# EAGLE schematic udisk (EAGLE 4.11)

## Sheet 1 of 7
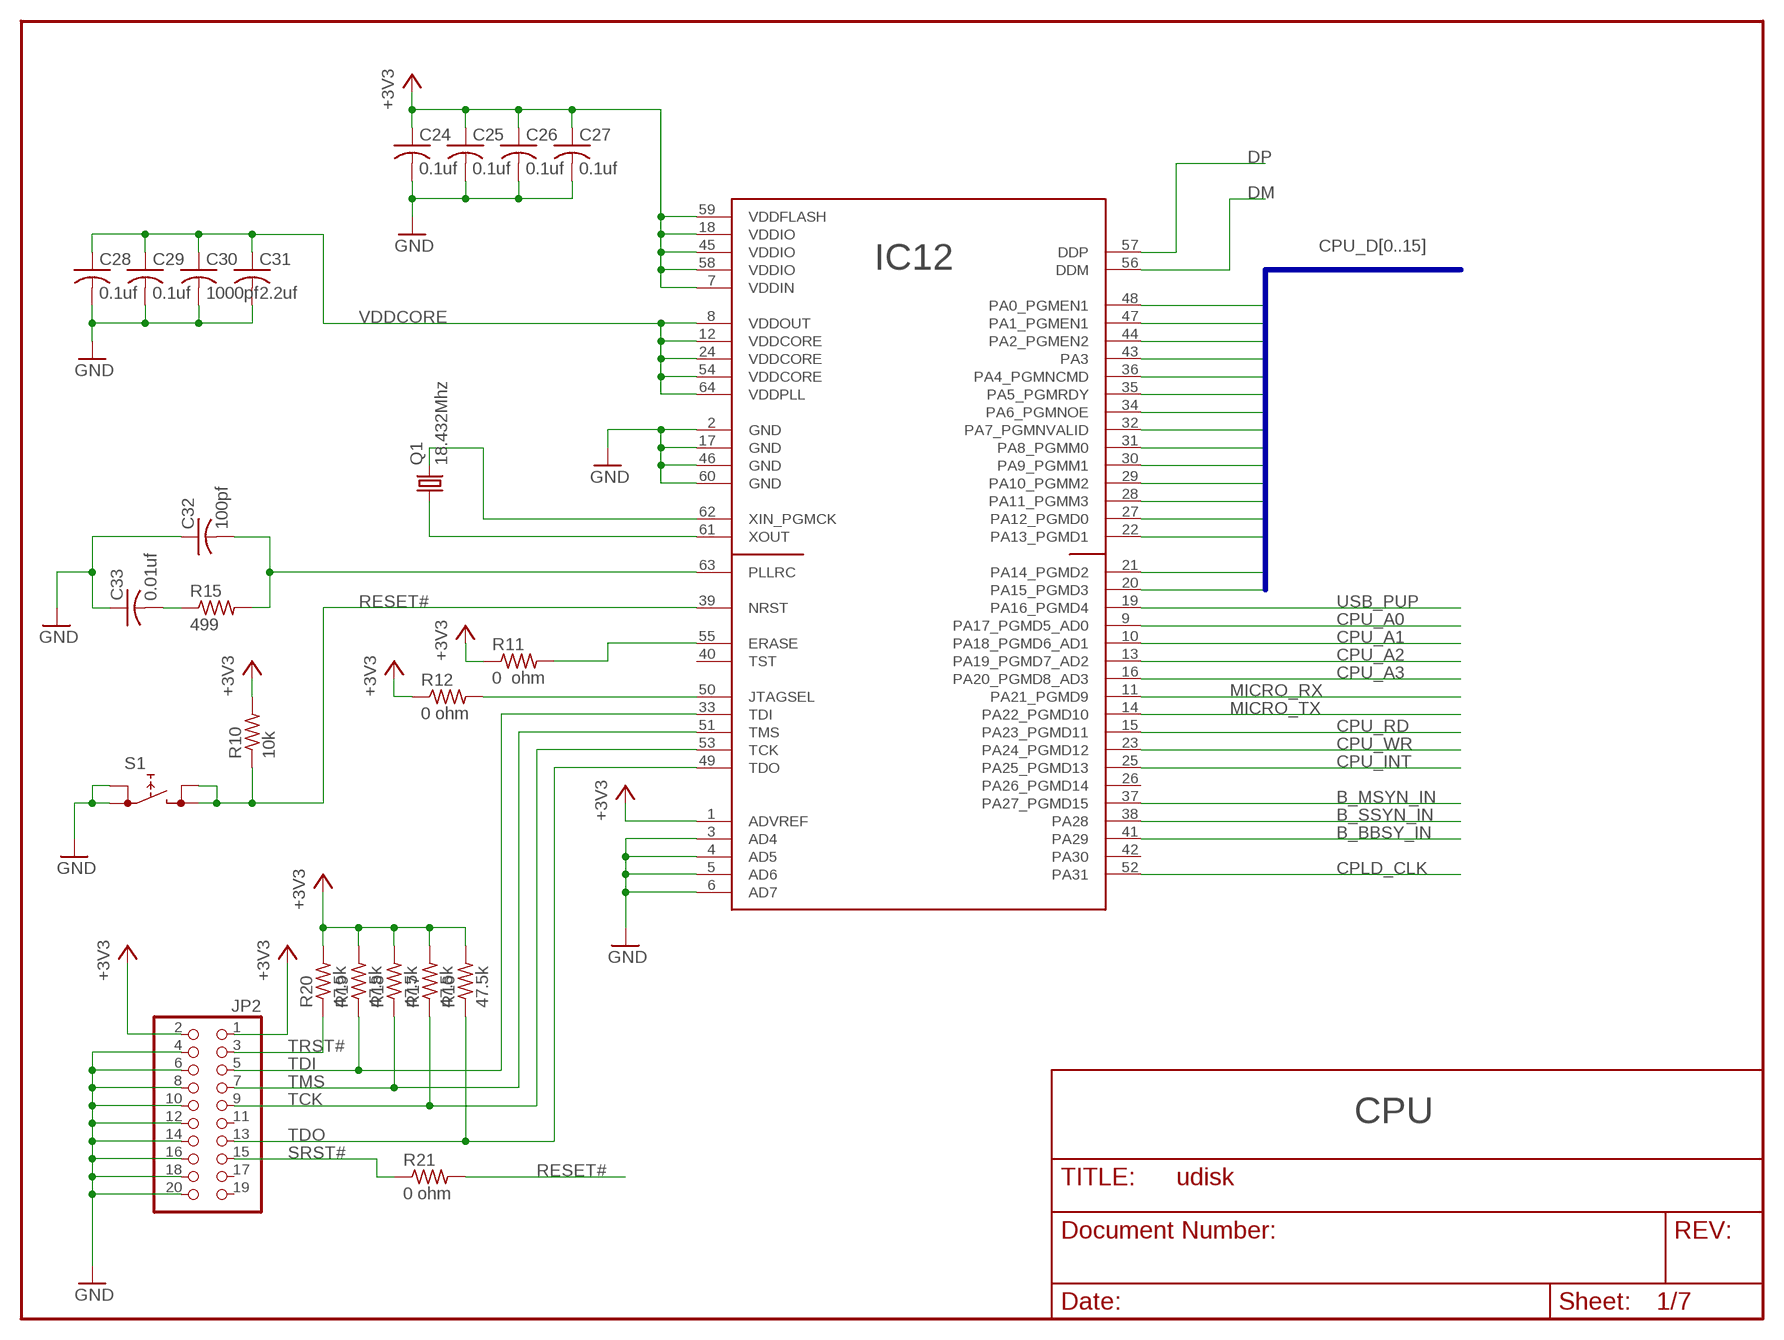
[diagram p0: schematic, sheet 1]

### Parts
C24  0.1uf  C-USC0603  [C0603]
C25  0.1uf  C-USC0603  [C0603]
C26  0.1uf  C-USC0603  [C0603]
C27  0.1uf  C-USC0603  [C0603]
C28  0.1uf  C-USC0603  [C0603]
C29  0.1uf  C-USC0603  [C0603]
C30  1000pf  C-USC0805  [C0805]
C31  2.2uf  C-USC1206  [C1206]
C32  100pf  C-USC0805  [C0805]
C33  0.01uf  C-USC0805  [C0805]
IC12  AT91SAM7S64_LQFP64  [LQFP64]
JP2  PINHD-2X10  [2X10]
Q1  18.432Mhz  CTS406  [SM406]
R10  10k  R-US_R0805  [R0805]
R11  0 ohm  R-US_R0805  [R0805]
R12  0 ohm  R-US_R0805  [R0805]
R15  499  R-US_M0805  [M0805]
R16  47.5k  R-US_R0805  [R0805]
R17  47.5k  R-US_R0805  [R0805]
R18  47.5k  R-US_R0805  [R0805]
R19  47.5k  R-US_R0805  [R0805]
R20  47.5k  R-US_R0805  [R0805]
R21  0 ohm  R-US_R0805  [R0805]
S1  KSC241J  [KSC241J]

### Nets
+3V3: C24.1 C25.1 C26.1 C27.1 IC12.1(ADVREF) IC12.7(VDDIN) IC12.18(VDDIO) IC12.45(VDDIO) IC12.58(VDDIO) IC12.59(VDDFLASH) JP2.1 JP2.2 R10.2 R11.1 R12.1 R16.2 R17.2 R18.2 R19.2 R20.2 ; also sheet 2,5,6,7
B_BBSY_IN: IC12.41(PA29) ; also sheet 2,3
B_MSYN_IN: IC12.37(PA27_PGMD15) ; also sheet 2,3
B_SSYN_IN: IC12.38(PA28) ; also sheet 2,3
CPLD_CLK: IC12.52(PA31) ; also sheet 2
CPU_A0: IC12.9(PA17_PGMD5_AD0) ; also sheet 2,6
CPU_A1: IC12.10(PA18_PGMD6_AD1) ; also sheet 2,6
CPU_A2: IC12.13(PA19_PGMD7_AD2) ; also sheet 2,6
CPU_A3: IC12.16(PA20_PGMD8_AD3) ; also sheet 2
CPU_D0: IC12.48(PA0_PGMEN1) ; also sheet 2,6
CPU_D1: IC12.47(PA1_PGMEN1) ; also sheet 2,6
CPU_D2: IC12.44(PA2_PGMEN2) ; also sheet 2,6
CPU_D3: IC12.43(PA3) ; also sheet 2,6
CPU_D4: IC12.36(PA4_PGMNCMD) ; also sheet 2,6
CPU_D5: IC12.35(PA5_PGMRDY) ; also sheet 2,6
CPU_D6: IC12.34(PA6_PGMNOE) ; also sheet 2,6
CPU_D7: IC12.32(PA7_PGMNVALID) ; also sheet 2,6
CPU_D8: IC12.31(PA8_PGMM0) ; also sheet 2,6
CPU_D9: IC12.30(PA9_PGMM1) ; also sheet 2,6
CPU_D10: IC12.29(PA10_PGMM2) ; also sheet 2,6
CPU_D11: IC12.28(PA11_PGMM3) ; also sheet 2,6
CPU_D12: IC12.27(PA12_PGMD0) ; also sheet 2,6
CPU_D13: IC12.22(PA13_PGMD1) ; also sheet 2,6
CPU_D14: IC12.21(PA14_PGMD2) ; also sheet 2,6
CPU_D15: IC12.20(PA15_PGMD3) ; also sheet 2,6
CPU_INT: IC12.25(PA25_PGMD13) ; also sheet 2
CPU_RD: IC12.15(PA23_PGMD11) ; also sheet 2
CPU_WR: IC12.23(PA24_PGMD12) ; also sheet 2
DM: IC12.56(DDM) ; also sheet 7
DP: IC12.57(DDP) ; also sheet 7
GND: C24.2 C25.2 C26.2 C27.2 C28.2 C29.2 C30.2 C31.2 C32.1 C33.1 IC12.2(GND) IC12.3(AD4) IC12.4(AD5) IC12.5(AD6) IC12.6(AD7) IC12.17(GND) IC12.46(GND) IC12.60(GND) JP2.4 JP2.6 JP2.8 JP2.10 JP2.12 JP2.14 JP2.16 JP2.18 JP2.20 S1.P1 S1.P2 ; also sheet 2,3,4,5,6,7
MICRO_RX: IC12.11(PA21_PGMD9) ; also sheet 5
MICRO_TX: IC12.14(PA22_PGMD10) ; also sheet 5
N$21: IC12.55(ERASE) R11.2
N$22: IC12.50(JTAGSEL) R12.2
N$24: IC12.62(XIN_PGMCK) Q1.3
N$29: IC12.61(XOUT) Q1.1
N$30: C32.2 IC12.63(PLLRC) R15.2
N$32: C33.2 R15.1
RESET#: IC12.39(NRST) R10.1 R21.2 S1.P3 S1.P4
SRST#: JP2.15 R21.1
TCK: IC12.53(TCK) JP2.9 R17.1
TDI: IC12.33(TDI) JP2.5 R19.1
TDO: IC12.49(TDO) JP2.13 R16.1
TMS: IC12.51(TMS) JP2.7 R18.1
TRST#: JP2.3 R20.1
USB_PUP: IC12.19(PA16_PGMD4) ; also sheet 7
VDDCORE: C28.1 C29.1 C30.1 C31.1 IC12.8(VDDOUT) IC12.12(VDDCORE) IC12.24(VDDCORE) IC12.54(VDDCORE) IC12.64(VDDPLL)
Unconnected: IC12.26(PA26_PGMD14) IC12.40(TST) IC12.42(PA30) JP2.11 JP2.17 JP2.19

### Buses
CPU_D[0..15]

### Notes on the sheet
- CPU

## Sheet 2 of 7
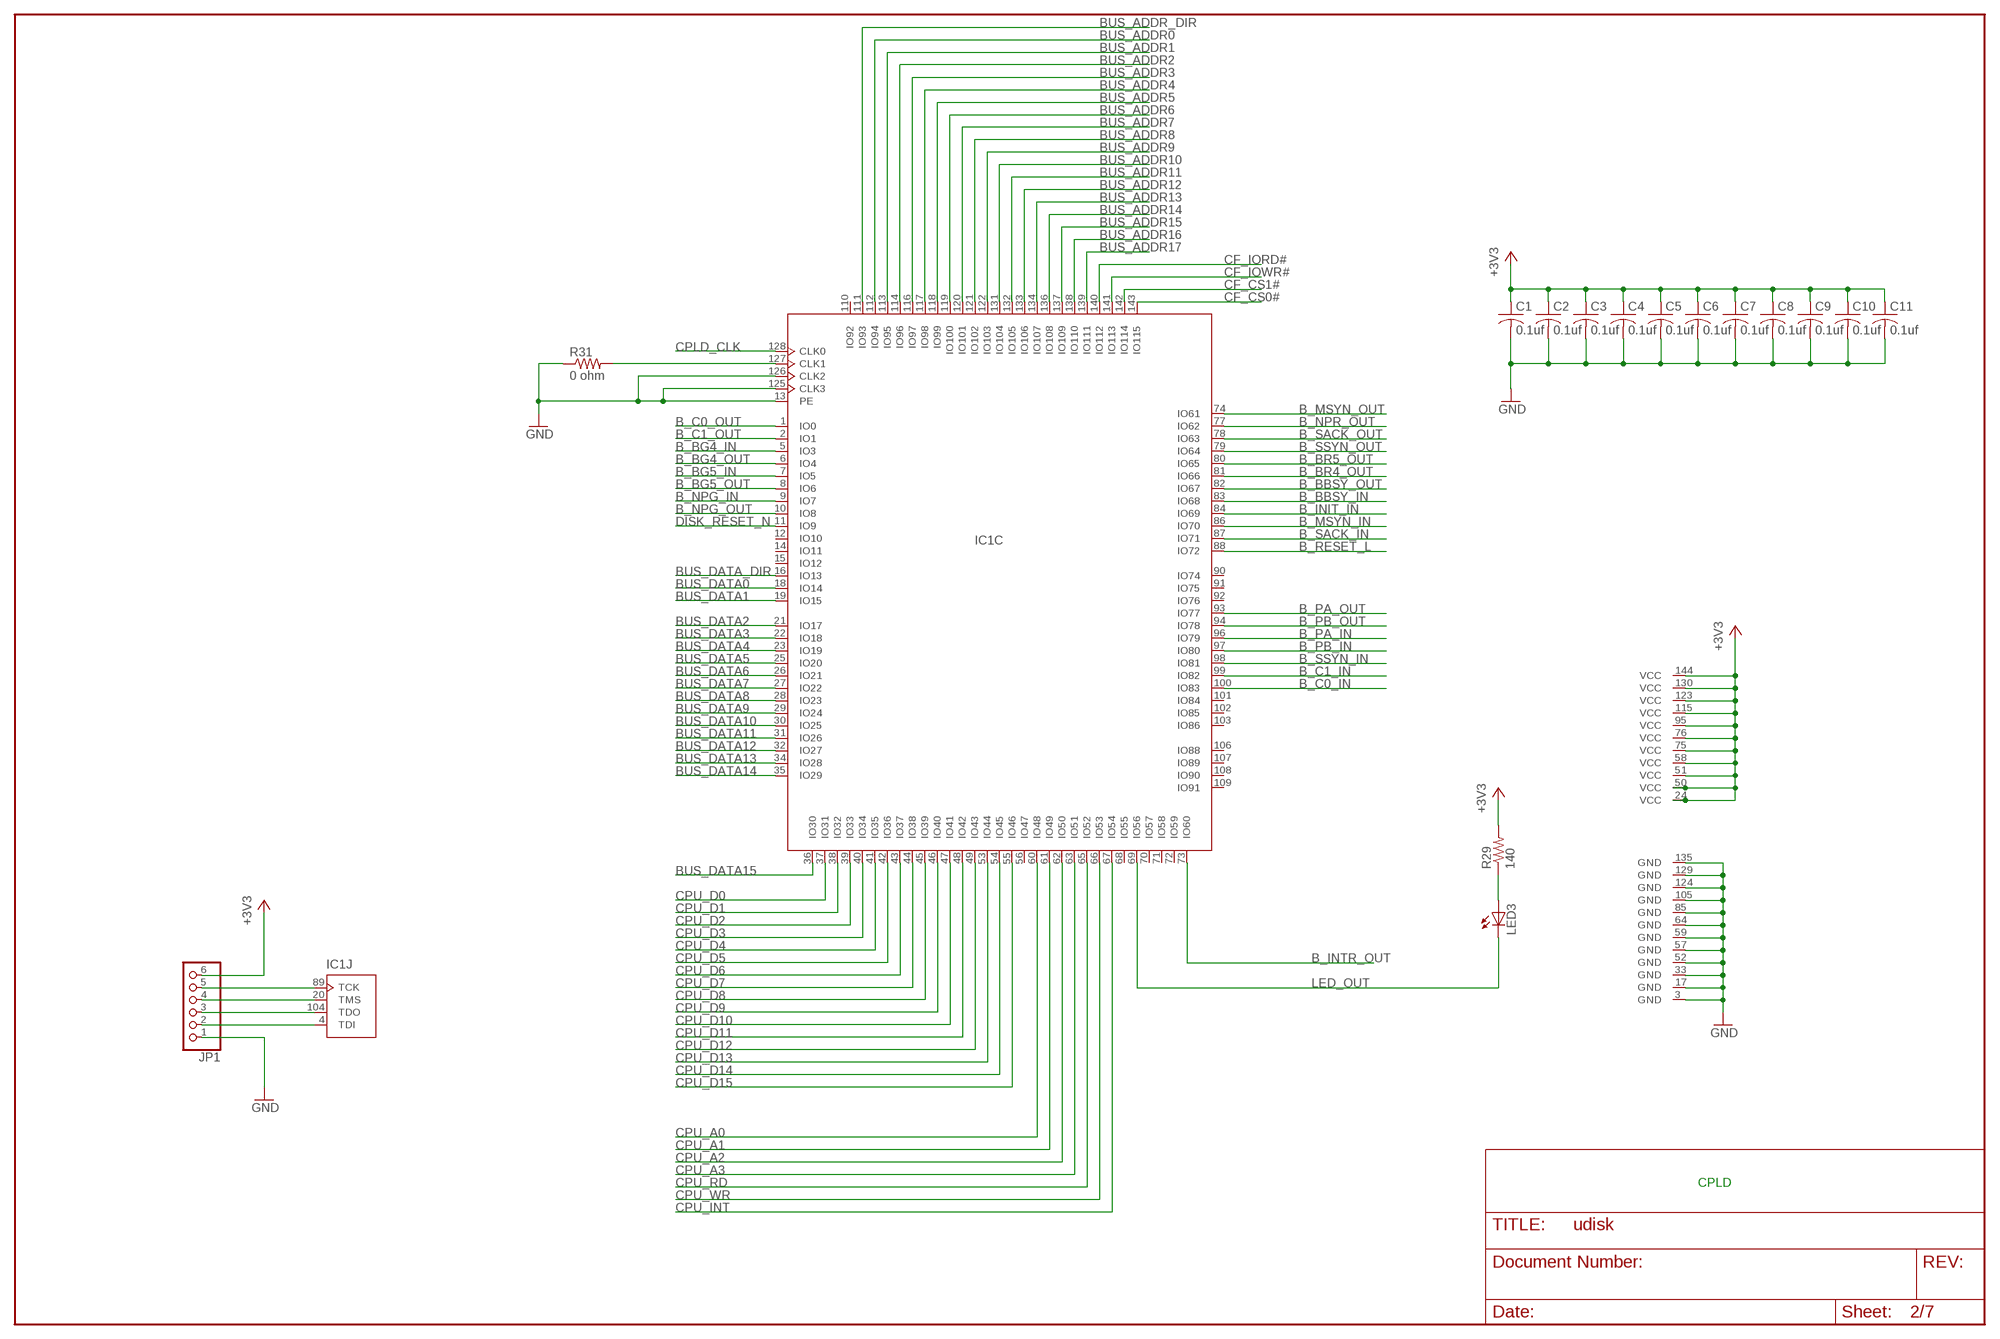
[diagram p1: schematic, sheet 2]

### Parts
C1  0.1uf  C-USC0603  [C0603]
C2  0.1uf  C-USC0603  [C0603]
C3  0.1uf  C-USC0603  [C0603]
C4  0.1uf  C-USC0603  [C0603]
C5  0.1uf  C-USC0603  [C0603]
C6  0.1uf  C-USC0603  [C0603]
C7  0.1uf  C-USC0603  [C0603]
C8  0.1uf  C-USC0603  [C0603]
C9  0.1uf  C-USC0603  [C0603]
C10  0.1uf  C-USC0603  [C0603]
C11  0.1uf  C-USC0603  [C0603]
IC1  XCR3256XLTQ144  [TQ144]
JP1  PINHD-1X6  [1X06]
LED3  LEDB156  [Q62902-B156]
R29  140  R-US_R0805  [R0805]
R31  0 ohm  R-US_R0805  [R0805]

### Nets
+3V3: C1.1 C2.1 C3.1 C4.1 C5.1 C6.1 C7.1 C8.1 C9.1 C10.1 C11.1 IC1.24(V1:VCC) IC1.50(V2:VCC) IC1.51(V3:VCC) IC1.58(V4:VCC) IC1.75(V5:VCC) IC1.76(V6:VCC) IC1.95(V7:VCC) IC1.115(V8:VCC) IC1.123(V9:VCC) IC1.130(V10:VCC) IC1.144(V11:VCC) JP1.6 R29.2 ; also sheet 1,5,6,7
B_BBSY_IN: IC1.83(C:IO68) ; also sheet 1,3
B_BBSY_OUT: IC1.82(C:IO67) ; also sheet 3
B_BG4_IN: IC1.5(C:IO3) ; also sheet 3
B_BG4_OUT: IC1.6(C:IO4) ; also sheet 3
B_BG5_IN: IC1.7(C:IO5) ; also sheet 3
B_BG5_OUT: IC1.8(C:IO6) ; also sheet 3
B_BR4_OUT: IC1.81(C:IO66) ; also sheet 3
B_BR5_OUT: IC1.80(C:IO65) ; also sheet 3
B_C0_IN: IC1.100(C:IO83) ; also sheet 3
B_C0_OUT: IC1.1(C:IO0) ; also sheet 3
B_C1_IN: IC1.99(C:IO82) ; also sheet 3
B_C1_OUT: IC1.2(C:IO1) ; also sheet 3
B_INIT_IN: IC1.84(C:IO69) ; also sheet 3
B_INTR_OUT: IC1.73(C:IO60) ; also sheet 3
B_MSYN_IN: IC1.86(C:IO70) ; also sheet 1,3
B_MSYN_OUT: IC1.74(C:IO61) ; also sheet 3
B_NPG_IN: IC1.9(C:IO7) ; also sheet 3
B_NPG_OUT: IC1.10(C:IO8) ; also sheet 3
B_NPR_OUT: IC1.77(C:IO62) ; also sheet 3
B_PA_IN: IC1.96(C:IO79) ; also sheet 3
B_PA_OUT: IC1.93(C:IO77) ; also sheet 3
B_PB_IN: IC1.97(C:IO80) ; also sheet 3
B_PB_OUT: IC1.94(C:IO78) ; also sheet 3
B_RESET_L: IC1.88(C:IO72)
B_SACK_IN: IC1.87(C:IO71) ; also sheet 3
B_SACK_OUT: IC1.78(C:IO63) ; also sheet 3
B_SSYN_IN: IC1.98(C:IO81) ; also sheet 1,3
B_SSYN_OUT: IC1.79(C:IO64) ; also sheet 3
BUS_ADDR0: IC1.112(C:IO94) ; also sheet 3
BUS_ADDR1: IC1.113(C:IO95) ; also sheet 3
BUS_ADDR2: IC1.114(C:IO96) ; also sheet 3
BUS_ADDR3: IC1.116(C:IO97) ; also sheet 3
BUS_ADDR4: IC1.117(C:IO98) ; also sheet 3
BUS_ADDR5: IC1.118(C:IO99) ; also sheet 3
BUS_ADDR6: IC1.119(C:IO100) ; also sheet 3
BUS_ADDR7: IC1.120(C:IO101) ; also sheet 3
BUS_ADDR8: IC1.121(C:IO102) ; also sheet 3
BUS_ADDR9: IC1.122(C:IO103) ; also sheet 3
BUS_ADDR10: IC1.131(C:IO104) ; also sheet 3
BUS_ADDR11: IC1.132(C:IO105) ; also sheet 3
BUS_ADDR12: IC1.133(C:IO106) ; also sheet 3
BUS_ADDR13: IC1.134(C:IO107) ; also sheet 3
BUS_ADDR14: IC1.136(C:IO108) ; also sheet 3
BUS_ADDR15: IC1.137(C:IO109) ; also sheet 3
BUS_ADDR16: IC1.138(C:IO110) ; also sheet 3
BUS_ADDR17: IC1.139(C:IO111) ; also sheet 3
BUS_ADDR_DIR: IC1.111(C:IO93) ; also sheet 3
BUS_DATA0: IC1.18(C:IO14) ; also sheet 3
BUS_DATA1: IC1.19(C:IO15) ; also sheet 3
BUS_DATA2: IC1.21(C:IO17) ; also sheet 3
BUS_DATA3: IC1.22(C:IO18) ; also sheet 3
BUS_DATA4: IC1.23(C:IO19) ; also sheet 3
BUS_DATA5: IC1.25(C:IO20) ; also sheet 3
BUS_DATA6: IC1.26(C:IO21) ; also sheet 3
BUS_DATA7: IC1.27(C:IO22) ; also sheet 3
BUS_DATA8: IC1.28(C:IO23) ; also sheet 3
BUS_DATA9: IC1.29(C:IO24) ; also sheet 3
BUS_DATA10: IC1.30(C:IO25) ; also sheet 3
BUS_DATA11: IC1.31(C:IO26) ; also sheet 3
BUS_DATA12: IC1.32(C:IO27) ; also sheet 3
BUS_DATA13: IC1.34(C:IO28) ; also sheet 3
BUS_DATA14: IC1.35(C:IO29) ; also sheet 3
BUS_DATA15: IC1.36(C:IO30) ; also sheet 3
BUS_DATA_DIR: IC1.16(C:IO13) ; also sheet 3
CF_CS0#: IC1.143(C:IO115) ; also sheet 6
CF_CS1#: IC1.142(C:IO114) ; also sheet 6
CF_IORD#: IC1.140(C:IO112) ; also sheet 6
CF_IOWR#: IC1.141(C:IO113) ; also sheet 6
CPLD_CLK: IC1.128(C:CLK0) ; also sheet 1
CPU_A0: IC1.60(C:IO48) ; also sheet 1,6
CPU_A1: IC1.61(C:IO49) ; also sheet 1,6
CPU_A2: IC1.62(C:IO50) ; also sheet 1,6
CPU_A3: IC1.63(C:IO51) ; also sheet 1
CPU_D0: IC1.37(C:IO31) ; also sheet 1,6
CPU_D1: IC1.38(C:IO32) ; also sheet 1,6
CPU_D2: IC1.39(C:IO33) ; also sheet 1,6
CPU_D3: IC1.40(C:IO34) ; also sheet 1,6
CPU_D4: IC1.41(C:IO35) ; also sheet 1,6
CPU_D5: IC1.42(C:IO36) ; also sheet 1,6
CPU_D6: IC1.43(C:IO37) ; also sheet 1,6
CPU_D7: IC1.44(C:IO38) ; also sheet 1,6
CPU_D8: IC1.45(C:IO39) ; also sheet 1,6
CPU_D9: IC1.46(C:IO40) ; also sheet 1,6
CPU_D10: IC1.47(C:IO41) ; also sheet 1,6
CPU_D11: IC1.48(C:IO42) ; also sheet 1,6
CPU_D12: IC1.49(C:IO43) ; also sheet 1,6
CPU_D13: IC1.53(C:IO44) ; also sheet 1,6
CPU_D14: IC1.54(C:IO45) ; also sheet 1,6
CPU_D15: IC1.55(C:IO46) ; also sheet 1,6
CPU_INT: IC1.67(C:IO54) ; also sheet 1
CPU_RD: IC1.65(C:IO52) ; also sheet 1
CPU_WR: IC1.66(C:IO53) ; also sheet 1
DISK_RESET_N: IC1.11(C:IO9) ; also sheet 6
GND: C1.2 C2.2 C3.2 C4.2 C5.2 C6.2 C7.2 C8.2 C9.2 C10.2 C11.2 IC1.3(GND) IC1.13(C:PE) IC1.17(GND) IC1.33(GND) IC1.52(GND) IC1.57(GND) IC1.59(GND) IC1.64(GND) IC1.85(GND) IC1.105(GND) IC1.124(GND) IC1.125(C:CLK3) IC1.126(C:CLK2) IC1.129(GND) IC1.135(GND) JP1.1 R31.1 ; also sheet 1,3,4,5,6,7
LED_OUT: IC1.69(C:IO56) LED3.K(C)
N$3: LED3.A R29.1
N$5: IC1.127(C:CLK1) R31.2
N$13: IC1.89(J:TCK) JP1.5
N$14: IC1.20(J:TMS) JP1.4
N$15: IC1.104(J:TDO) JP1.3
N$16: IC1.4(J:TDI) JP1.2
Unconnected: IC1.12(C:IO10) IC1.14(C:IO11) IC1.15(C:IO12) IC1.56(C:IO47) IC1.68(C:IO55) IC1.70(C:IO57) IC1.71(C:IO58) IC1.72(C:IO59) IC1.90(C:IO74) IC1.91(C:IO75) IC1.92(C:IO76) IC1.101(C:IO84) IC1.102(C:IO85) IC1.103(C:IO86) IC1.106(C:IO88) IC1.107(C:IO89) IC1.108(C:IO90) IC1.109(C:IO91) IC1.110(C:IO92)

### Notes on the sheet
- CPLD

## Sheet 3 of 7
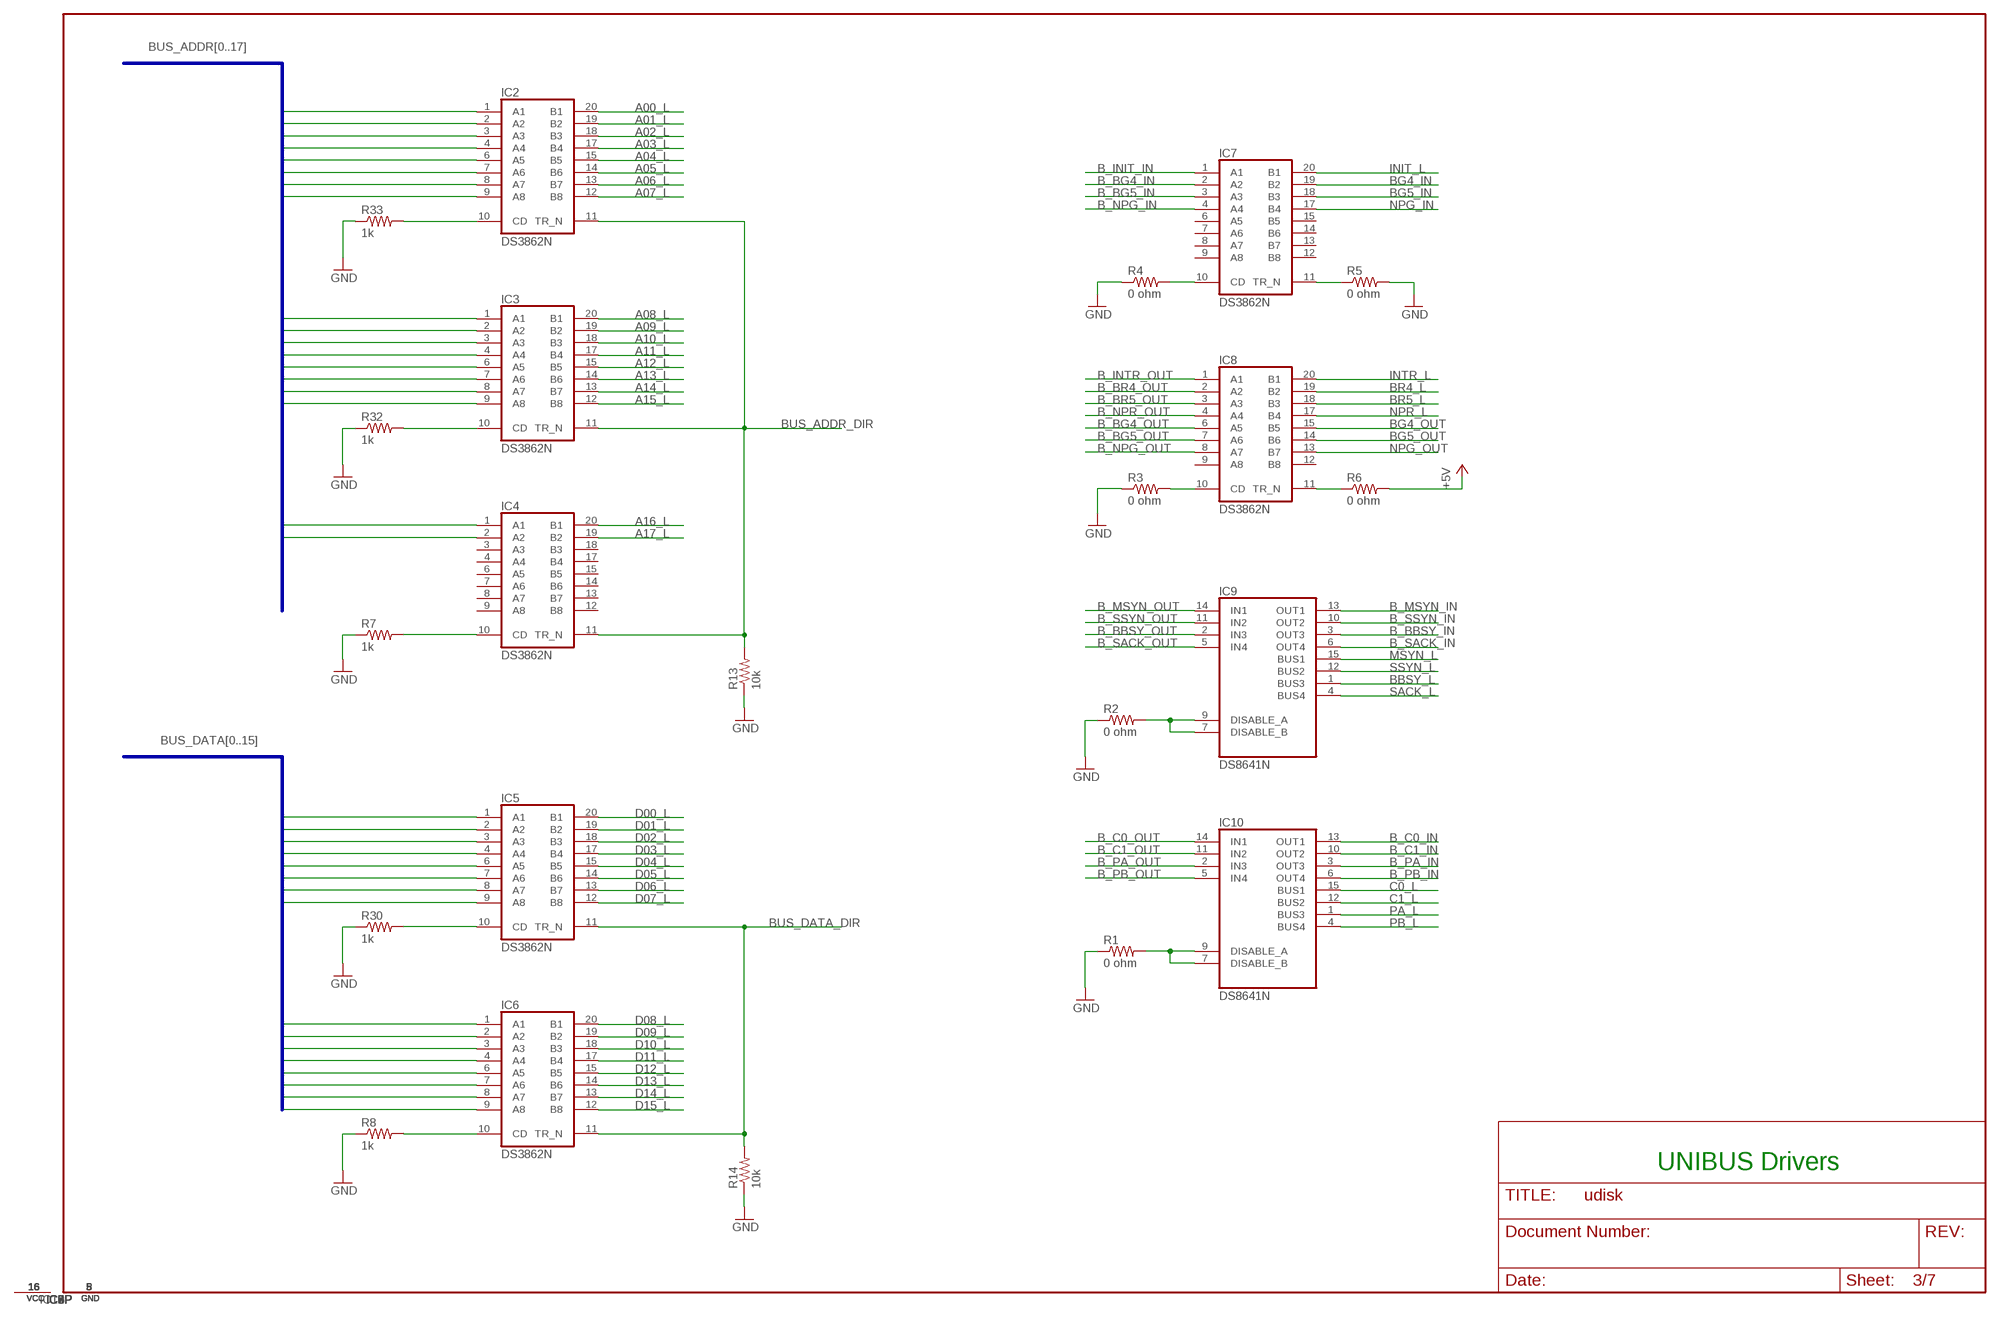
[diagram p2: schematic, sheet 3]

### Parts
IC2  DS3862N  [DIL20]
IC3  DS3862N  [DIL20]
IC4  DS3862N  [DIL20]
IC5  DS3862N  [DIL20]
IC6  DS3862N  [DIL20]
IC7  DS3862N  [DIL20]
IC8  DS3862N  [DIL20]
IC9  DS8641N  [DIL16]
IC10  DS8641N  [DIL16]
R1  0 ohm  R-US_R0805  [R0805]
R2  0 ohm  R-US_R0805  [R0805]
R3  0 ohm  R-US_R0805  [R0805]
R4  0 ohm  R-US_R0805  [R0805]
R5  0 ohm  R-US_R0805  [R0805]
R6  0 ohm  R-US_R0805  [R0805]
R7  1k  R-US_R0805  [R0805]
R8  1k  R-US_R0805  [R0805]
R13  10k  R-US_R0805  [R0805]
R14  10k  R-US_R0805  [R0805]
R30  1k  R-US_R0805  [R0805]
R32  1k  R-US_R0805  [R0805]
R33  1k  R-US_R0805  [R0805]

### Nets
+5V: R6.2 ; also sheet 4,5,6
A00_L: IC2.20(B1) ; also sheet 4
A01_L: IC2.19(B2) ; also sheet 4
A02_L: IC2.18(B3) ; also sheet 4
A03_L: IC2.17(B4) ; also sheet 4
A04_L: IC2.15(B5) ; also sheet 4
A05_L: IC2.14(B6) ; also sheet 4
A06_L: IC2.13(B7) ; also sheet 4
A07_L: IC2.12(B8) ; also sheet 4
A08_L: IC3.20(B1) ; also sheet 4
A09_L: IC3.19(B2) ; also sheet 4
A10_L: IC3.18(B3) ; also sheet 4
A11_L: IC3.17(B4) ; also sheet 4
A12_L: IC3.15(B5) ; also sheet 4
A13_L: IC3.14(B6) ; also sheet 4
A14_L: IC3.13(B7) ; also sheet 4
A15_L: IC3.12(B8) ; also sheet 4
A16_L: IC4.20(B1) ; also sheet 4
A17_L: IC4.19(B2) ; also sheet 4
B_BBSY_IN: IC9.3(OUT3) ; also sheet 1,2
B_BBSY_OUT: IC9.2(IN3) ; also sheet 2
B_BG4_IN: IC7.2(A2) ; also sheet 2
B_BG4_OUT: IC8.6(A5) ; also sheet 2
B_BG5_IN: IC7.3(A3) ; also sheet 2
B_BG5_OUT: IC8.7(A6) ; also sheet 2
B_BR4_OUT: IC8.2(A2) ; also sheet 2
B_BR5_OUT: IC8.3(A3) ; also sheet 2
B_C0_IN: IC10.13(OUT1) ; also sheet 2
B_C0_OUT: IC10.14(IN1) ; also sheet 2
B_C1_IN: IC10.10(OUT2) ; also sheet 2
B_C1_OUT: IC10.11(IN2) ; also sheet 2
B_INIT_IN: IC7.1(A1) ; also sheet 2
B_INTR_OUT: IC8.1(A1) ; also sheet 2
B_MSYN_IN: IC9.13(OUT1) ; also sheet 1,2
B_MSYN_OUT: IC9.14(IN1) ; also sheet 2
B_NPG_IN: IC7.4(A4) ; also sheet 2
B_NPG_OUT: IC8.8(A7) ; also sheet 2
B_NPR_OUT: IC8.4(A4) ; also sheet 2
B_PA_IN: IC10.3(OUT3) ; also sheet 2
B_PA_OUT: IC10.2(IN3) ; also sheet 2
B_PB_IN: IC10.6(OUT4) ; also sheet 2
B_PB_OUT: IC10.5(IN4) ; also sheet 2
B_SACK_IN: IC9.6(OUT4) ; also sheet 2
B_SACK_OUT: IC9.5(IN4) ; also sheet 2
B_SSYN_IN: IC9.10(OUT2) ; also sheet 1,2
B_SSYN_OUT: IC9.11(IN2) ; also sheet 2
BBSY_L: IC9.1(BUS3) ; also sheet 4
BG4_IN: IC7.19(B2) ; also sheet 4
BG4_OUT: IC8.15(B5) ; also sheet 4
BG5_IN: IC7.18(B3) ; also sheet 4
BG5_OUT: IC8.14(B6) ; also sheet 4
BR4_L: IC8.19(B2) ; also sheet 4
BR5_L: IC8.18(B3) ; also sheet 4
BUS_ADDR0: IC2.1(A1) ; also sheet 2
BUS_ADDR1: IC2.2(A2) ; also sheet 2
BUS_ADDR2: IC2.3(A3) ; also sheet 2
BUS_ADDR3: IC2.4(A4) ; also sheet 2
BUS_ADDR4: IC2.6(A5) ; also sheet 2
BUS_ADDR5: IC2.7(A6) ; also sheet 2
BUS_ADDR6: IC2.8(A7) ; also sheet 2
BUS_ADDR7: IC2.9(A8) ; also sheet 2
BUS_ADDR8: IC3.1(A1) ; also sheet 2
BUS_ADDR9: IC3.2(A2) ; also sheet 2
BUS_ADDR10: IC3.3(A3) ; also sheet 2
BUS_ADDR11: IC3.4(A4) ; also sheet 2
BUS_ADDR12: IC3.6(A5) ; also sheet 2
BUS_ADDR13: IC3.7(A6) ; also sheet 2
BUS_ADDR14: IC3.8(A7) ; also sheet 2
BUS_ADDR15: IC3.9(A8) ; also sheet 2
BUS_ADDR16: IC4.1(A1) ; also sheet 2
BUS_ADDR17: IC4.2(A2) ; also sheet 2
BUS_ADDR_DIR: IC2.11(TR_N) IC3.11(TR_N) IC4.11(TR_N) R13.2 ; also sheet 2
BUS_DATA0: IC5.1(A1) ; also sheet 2
BUS_DATA1: IC5.2(A2) ; also sheet 2
BUS_DATA2: IC5.3(A3) ; also sheet 2
BUS_DATA3: IC5.4(A4) ; also sheet 2
BUS_DATA4: IC5.6(A5) ; also sheet 2
BUS_DATA5: IC5.7(A6) ; also sheet 2
BUS_DATA6: IC5.8(A7) ; also sheet 2
BUS_DATA7: IC5.9(A8) ; also sheet 2
BUS_DATA8: IC6.1(A1) ; also sheet 2
BUS_DATA9: IC6.2(A2) ; also sheet 2
BUS_DATA10: IC6.3(A3) ; also sheet 2
BUS_DATA11: IC6.4(A4) ; also sheet 2
BUS_DATA12: IC6.6(A5) ; also sheet 2
BUS_DATA13: IC6.7(A6) ; also sheet 2
BUS_DATA14: IC6.8(A7) ; also sheet 2
BUS_DATA15: IC6.9(A8) ; also sheet 2
BUS_DATA_DIR: IC5.11(TR_N) IC6.11(TR_N) R14.2 ; also sheet 2
C0_L: IC10.15(BUS1) ; also sheet 4
C1_L: IC10.12(BUS2) ; also sheet 4
D00_L: IC5.20(B1) ; also sheet 4
D01_L: IC5.19(B2) ; also sheet 4
D02_L: IC5.18(B3) ; also sheet 4
D03_L: IC5.17(B4) ; also sheet 4
D04_L: IC5.15(B5) ; also sheet 4
D05_L: IC5.14(B6) ; also sheet 4
D06_L: IC5.13(B7) ; also sheet 4
D07_L: IC5.12(B8) ; also sheet 4
D08_L: IC6.20(B1) ; also sheet 4
D09_L: IC6.19(B2) ; also sheet 4
D10_L: IC6.18(B3) ; also sheet 4
D11_L: IC6.17(B4) ; also sheet 4
D12_L: IC6.15(B5) ; also sheet 4
D13_L: IC6.14(B6) ; also sheet 4
D14_L: IC6.13(B7) ; also sheet 4
D15_L: IC6.12(B8) ; also sheet 4
GND: R1.1 R2.1 R3.1 R4.1 R5.2 R7.1 R8.1 R13.1 R14.1 R30.1 R32.1 R33.1 ; also sheet 1,2,4,5,6,7
INIT_L: IC7.20(B1) ; also sheet 4
INTR_L: IC8.20(B1) ; also sheet 4
MSYN_L: IC9.15(BUS1) ; also sheet 4
N$1: IC9.7(DISABLE_B) IC9.9(DISABLE_A) R2.2
N$2: IC10.7(DISABLE_B) IC10.9(DISABLE_A) R1.2
N$7: IC7.10(CD) R4.2
N$8: IC8.10(CD) R3.2
N$9: IC7.11(TR_N) R5.1
N$10: IC8.11(TR_N) R6.1
N$11: IC4.10(CD) R7.2
N$12: IC6.10(CD) R8.2
N$18: IC5.10(CD) R30.2
N$20: IC2.10(CD) R33.2
N$25: IC3.10(CD) R32.2
NPG_IN: IC7.17(B4) ; also sheet 4
NPG_OUT: IC8.13(B7) ; also sheet 4
NPR_L: IC8.17(B4) ; also sheet 4
PA_L: IC10.1(BUS3) ; also sheet 4
PB_L: IC10.4(BUS4) ; also sheet 4
SACK_L: IC9.4(BUS4) ; also sheet 4
SSYN_L: IC9.12(BUS2) ; also sheet 4

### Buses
BUS_ADDR[0..17]
BUS_DATA[0..15]

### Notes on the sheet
- UNIBUS Drivers

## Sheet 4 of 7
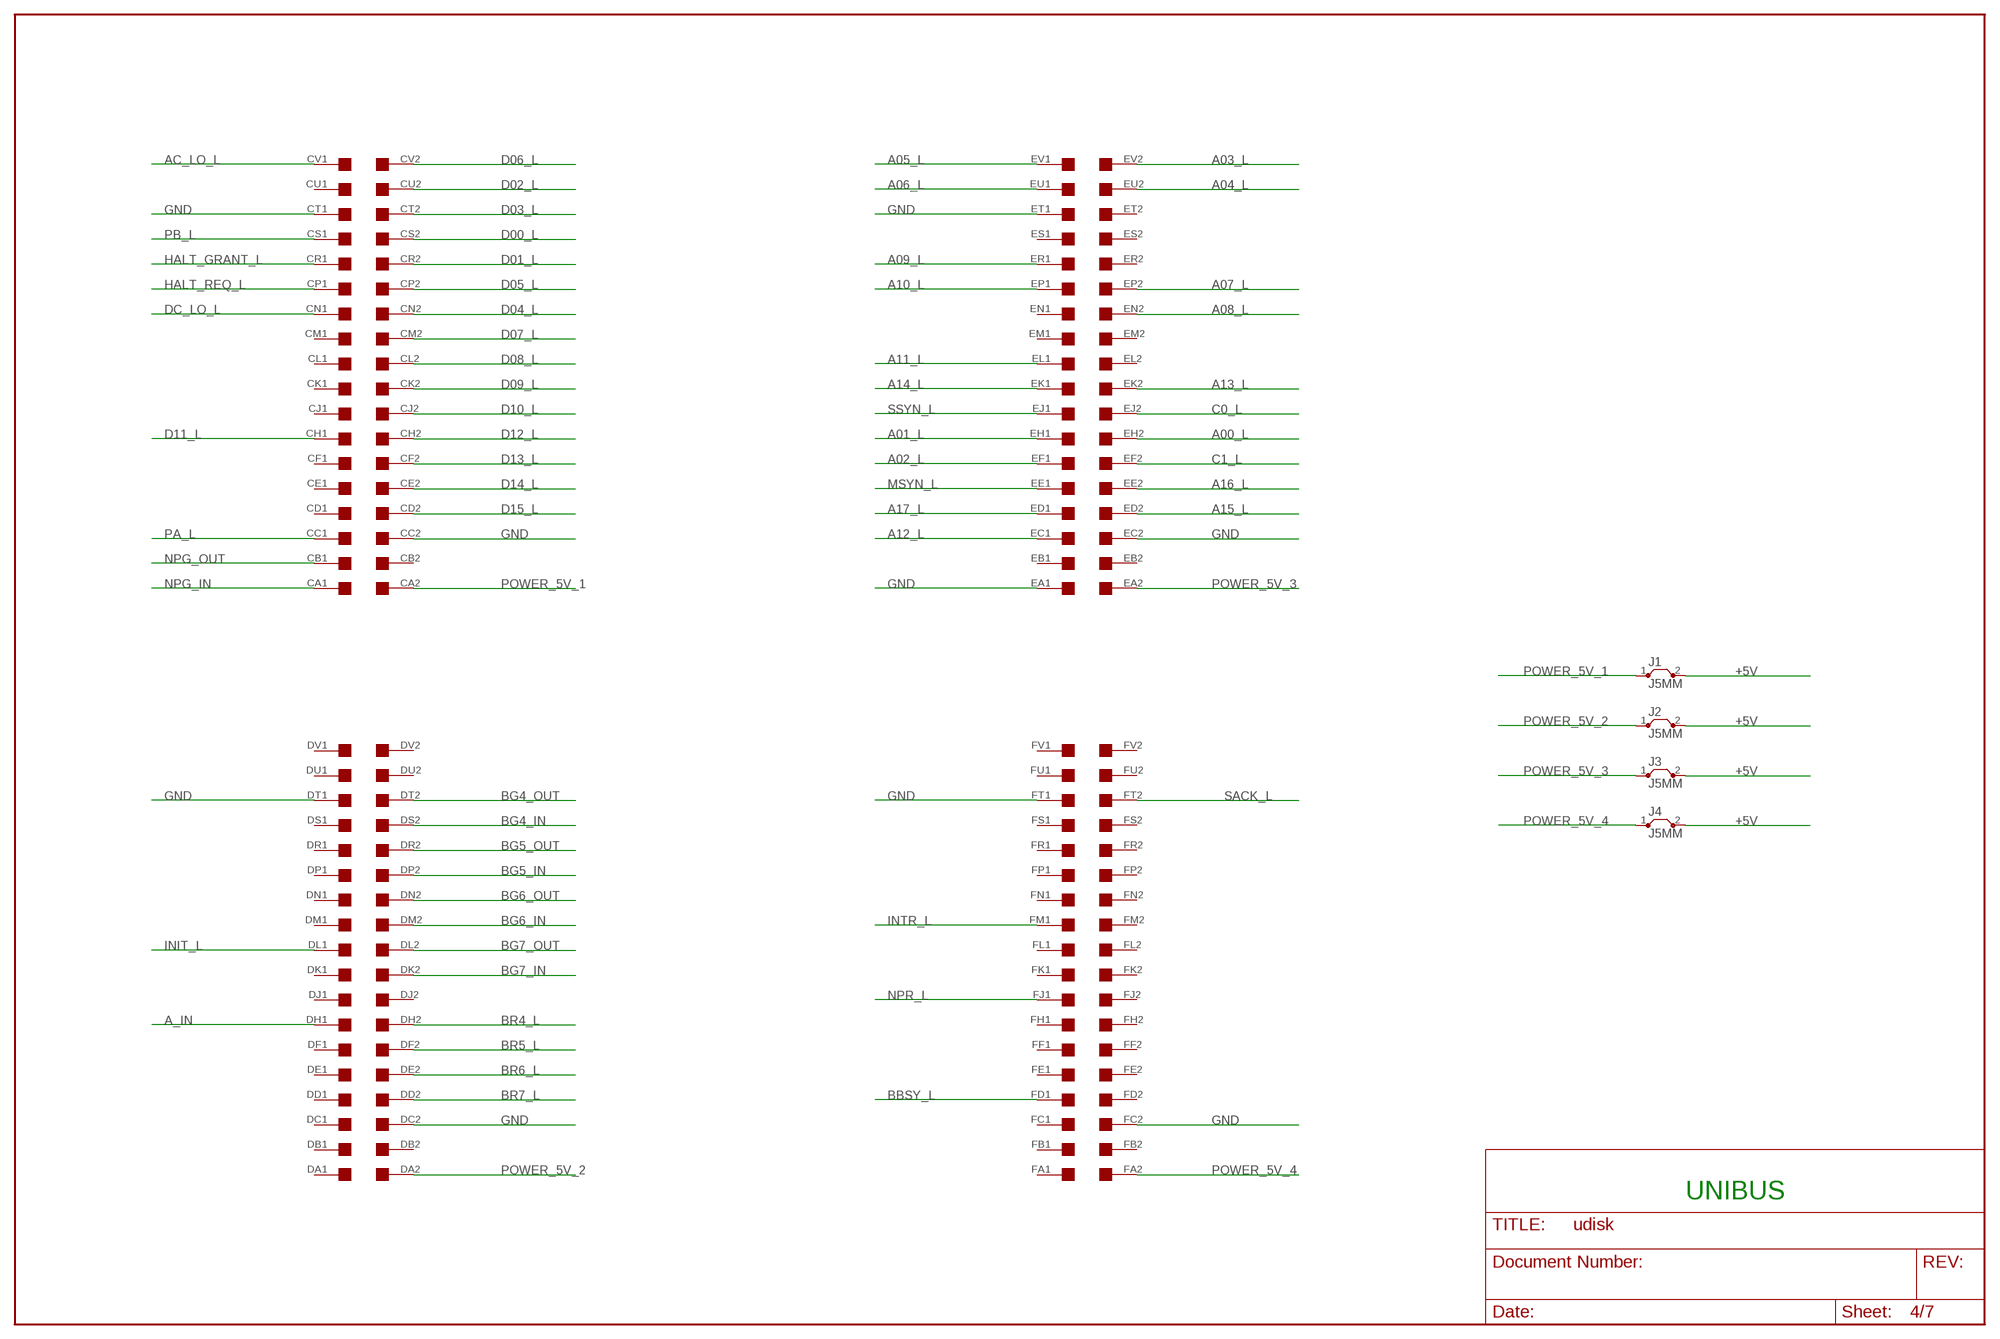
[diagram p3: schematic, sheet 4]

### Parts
J1  J5MM  [05]
J2  J5MM  [05]
J3  J5MM  [05]
J4  J5MM  [05]
U$1  QUAD-CDEF  [EDGE-CON8]

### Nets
+5V: J1.2 J2.2 J3.2 J4.2 ; also sheet 3,5,6
A00_L: U$1.EH2 ; also sheet 3
A01_L: U$1.EH1 ; also sheet 3
A02_L: U$1.EF1 ; also sheet 3
A03_L: U$1.EV2 ; also sheet 3
A04_L: U$1.EU2 ; also sheet 3
A05_L: U$1.EV1 ; also sheet 3
A06_L: U$1.EU1 ; also sheet 3
A07_L: U$1.EP2 ; also sheet 3
A08_L: U$1.EN2 ; also sheet 3
A09_L: U$1.ER1 ; also sheet 3
A10_L: U$1.EP1 ; also sheet 3
A11_L: U$1.EL1 ; also sheet 3
A12_L: U$1.EC1 ; also sheet 3
A13_L: U$1.EK2 ; also sheet 3
A14_L: U$1.EK1 ; also sheet 3
A15_L: U$1.ED2 ; also sheet 3
A16_L: U$1.EE2 ; also sheet 3
A17_L: U$1.ED1 ; also sheet 3
A_IN: U$1.DH1
AC_LO_L: U$1.CV1
BBSY_L: U$1.FD1 ; also sheet 3
BG4_IN: U$1.DS2 ; also sheet 3
BG4_OUT: U$1.DT2 ; also sheet 3
BG5_IN: U$1.DP2 ; also sheet 3
BG5_OUT: U$1.DR2 ; also sheet 3
BG6_IN: U$1.DM2
BG6_OUT: U$1.DN2
BG7_IN: U$1.DK2
BG7_OUT: U$1.DL2
BR4_L: U$1.DH2 ; also sheet 3
BR5_L: U$1.DF2 ; also sheet 3
BR6_L: U$1.DE2
BR7_L: U$1.DD2
C0_L: U$1.EJ2 ; also sheet 3
C1_L: U$1.EF2 ; also sheet 3
D00_L: U$1.CS2 ; also sheet 3
D01_L: U$1.CR2 ; also sheet 3
D02_L: U$1.CU2 ; also sheet 3
D03_L: U$1.CT2 ; also sheet 3
D04_L: U$1.CN2 ; also sheet 3
D05_L: U$1.CP2 ; also sheet 3
D06_L: U$1.CV2 ; also sheet 3
D07_L: U$1.CM2 ; also sheet 3
D08_L: U$1.CL2 ; also sheet 3
D09_L: U$1.CK2 ; also sheet 3
D10_L: U$1.CJ2 ; also sheet 3
D11_L: U$1.CH1 ; also sheet 3
D12_L: U$1.CH2 ; also sheet 3
D13_L: U$1.CF2 ; also sheet 3
D14_L: U$1.CE2 ; also sheet 3
D15_L: U$1.CD2 ; also sheet 3
DC_LO_L: U$1.CN1
GND: U$1.CC2 U$1.CT1 U$1.DC2 U$1.DT1 U$1.EA1 U$1.EC2 U$1.ET1 U$1.FC2 U$1.FT1 ; also sheet 1,2,3,5,6,7
HALT_GRANT_L: U$1.CR1
HALT_REQ_L: U$1.CP1
INIT_L: U$1.DL1 ; also sheet 3
INTR_L: U$1.FM1 ; also sheet 3
MSYN_L: U$1.EE1 ; also sheet 3
NPG_IN: U$1.CA1 ; also sheet 3
NPG_OUT: U$1.CB1 ; also sheet 3
NPR_L: U$1.FJ1 ; also sheet 3
PA_L: U$1.CC1 ; also sheet 3
PB_L: U$1.CS1 ; also sheet 3
POWER_5V_1: J1.1 U$1.CA2
POWER_5V_2: J2.1 U$1.DA2
POWER_5V_3: J3.1 U$1.EA2
POWER_5V_4: J4.1 U$1.FA2
SACK_L: U$1.FT2 ; also sheet 3
SSYN_L: U$1.EJ1 ; also sheet 3
Unconnected: U$1.CB2 U$1.CD1 U$1.CE1 U$1.CF1 U$1.CJ1 U$1.CK1 U$1.CL1 U$1.CM1 U$1.CU1 U$1.DA1 U$1.DB1 U$1.DB2 U$1.DC1 U$1.DD1 U$1.DE1 U$1.DF1 U$1.DJ1 U$1.DJ2 U$1.DK1 U$1.DM1 U$1.DN1 U$1.DP1 U$1.DR1 U$1.DS1 U$1.DU1 U$1.DU2 U$1.DV1 U$1.DV2 U$1.EB1 U$1.EB2 U$1.EL2 U$1.EM1 U$1.EM2 U$1.EN1 U$1.ER2 U$1.ES1 U$1.ES2 U$1.ET2 U$1.FA1 U$1.FB1 U$1.FB2 U$1.FC1 U$1.FD2 U$1.FE1 U$1.FE2 U$1.FF1 U$1.FF2 U$1.FH1 U$1.FH2 U$1.FJ2 U$1.FK1 U$1.FK2 U$1.FL1 U$1.FL2 U$1.FM2 U$1.FN1 U$1.FN2 U$1.FP1 U$1.FP2 U$1.FR1 U$1.FR2 U$1.FS1 U$1.FS2 U$1.FU1 U$1.FU2 U$1.FV1 U$1.FV2

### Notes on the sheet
- UNIBUS

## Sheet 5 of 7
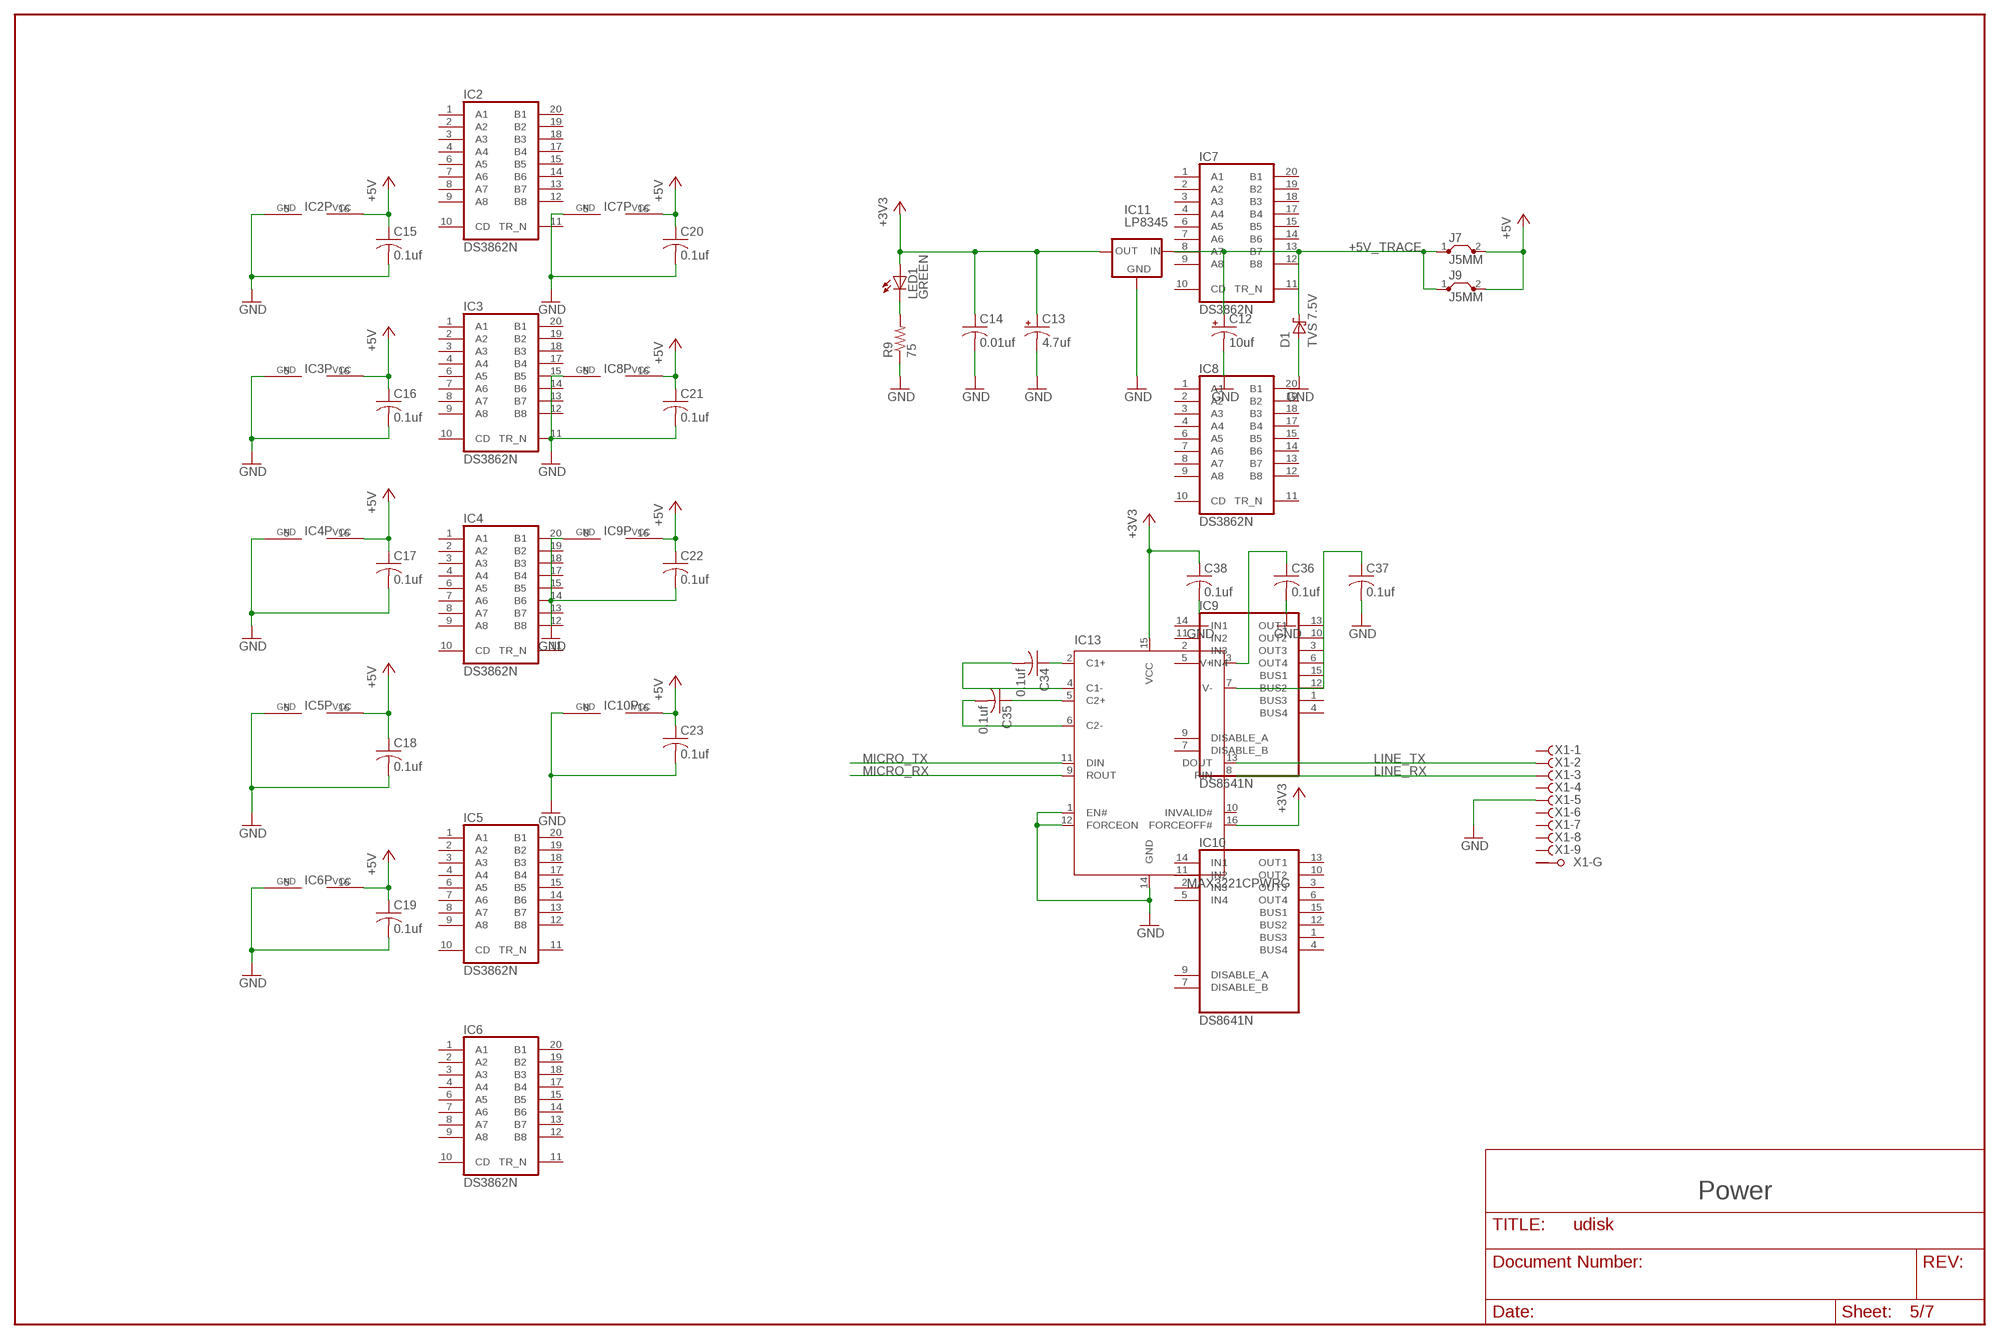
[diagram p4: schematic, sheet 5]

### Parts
C12  10uf  CPOL-USCT3216  [CT3216]
C13  4.7uf  CPOL-USCT3216  [CT3216]
C14  0.01uf  C-USC0805  [C0805]
C15  0.1uf  C-USC0603  [C0603]
C16  0.1uf  C-USC0603  [C0603]
C17  0.1uf  C-USC0603  [C0603]
C18  0.1uf  C-USC0603  [C0603]
C19  0.1uf  C-USC0603  [C0603]
C20  0.1uf  C-USC0603  [C0603]
C21  0.1uf  C-USC0603  [C0603]
C22  0.1uf  C-USC0603  [C0603]
C23  0.1uf  C-USC0603  [C0603]
C34  0.1uf  C-USC0603  [C0603]
C35  0.1uf  C-USC0603  [C0603]
C36  0.1uf  C-USC0603  [C0603]
C37  0.1uf  C-USC0603  [C0603]
C38  0.1uf  C-USC0603  [C0603]
D1  TVS 7.5V  1SMA16AT3  [SMA]
IC11  LP8345  [TO252]
IC13  MAX3221CPWRG  [TSSOP-16]
J7  J5MM  [05]
J9  J5MM  [05]
LED1  GREEN  LEDB156  [Q62902-B156]
R9  75  R-US_M0805  [M0805]
X1  F09HPS  [F09HP]

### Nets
+3V3: C13.+ C14.1 C38.1 IC11.1(OUT) IC13.15(VCC) IC13.16(FORCEOFF#) LED1.A ; also sheet 1,2,6,7
+5V: C15.1 C16.1 C17.1 C18.1 C19.1 C20.1 C21.1 C22.1 C23.1 IC2.16(VCC) IC3.16(VCC) IC4.16(VCC) IC5.16(VCC) IC6.16(VCC) IC7.16(VCC) IC8.16(VCC) IC9.16(VCC) IC10.16(VCC) J7.2 J9.2 ; also sheet 3,4,6
+5V_TRACE: C12.+ D1.1(K) IC11.2(IN) J7.1 J9.1
GND: C12.- C13.- C14.2 C15.2 C16.2 C17.2 C18.2 C19.2 C20.2 C21.2 C22.2 C23.2 C36.2 C37.2 C38.2 D1.2(A) IC2.5(GND) IC3.5(GND) IC4.5(GND) IC5.5(GND) IC6.5(GND) IC7.5(GND) IC8.5(GND) IC9.8(GND) IC10.8(GND) IC11.3(GND) IC13.1(EN#) IC13.12(FORCEON) IC13.14(GND) R9.1 X1.5(-5:F) ; also sheet 1,2,3,4,6,7
LINE_RX: IC13.8(RIN) X1.3(-3:F)
LINE_TX: IC13.13(DOUT) X1.2(-2:F)
MICRO_RX: IC13.9(ROUT) ; also sheet 1
MICRO_TX: IC13.11(DIN) ; also sheet 1
N$26: C35.1 IC13.5(C2+)
N$27: C34.1 IC13.2(C1+)
N$28: C34.2 IC13.4(C1-)
N$31: C35.2 IC13.6(C2-)
N$34: C36.1 IC13.3(V+)
N$35: C37.1 IC13.7(V-)
N$38: LED1.K(C) R9.2
Unconnected: IC4.3(A3) IC4.4(A4) IC4.6(A5) IC4.7(A6) IC4.8(A7) IC4.9(A8) IC4.12(B8) IC4.13(B7) IC4.14(B6) IC4.15(B5) IC4.17(B4) IC4.18(B3) IC7.6(A5) IC7.7(A6) IC7.8(A7) IC7.9(A8) IC7.12(B8) IC7.13(B7) IC7.14(B6) IC7.15(B5) IC8.9(A8) IC8.12(B8) IC13.10(INVALID#) X1.1(-1:F) X1.4(-4:F) X1.6(-6:F) X1.7(-7:F) X1.8(-8:F) X1.9(-9:F) X1.G1(-G:G1) X1.G2(-G:G2)

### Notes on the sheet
- Power

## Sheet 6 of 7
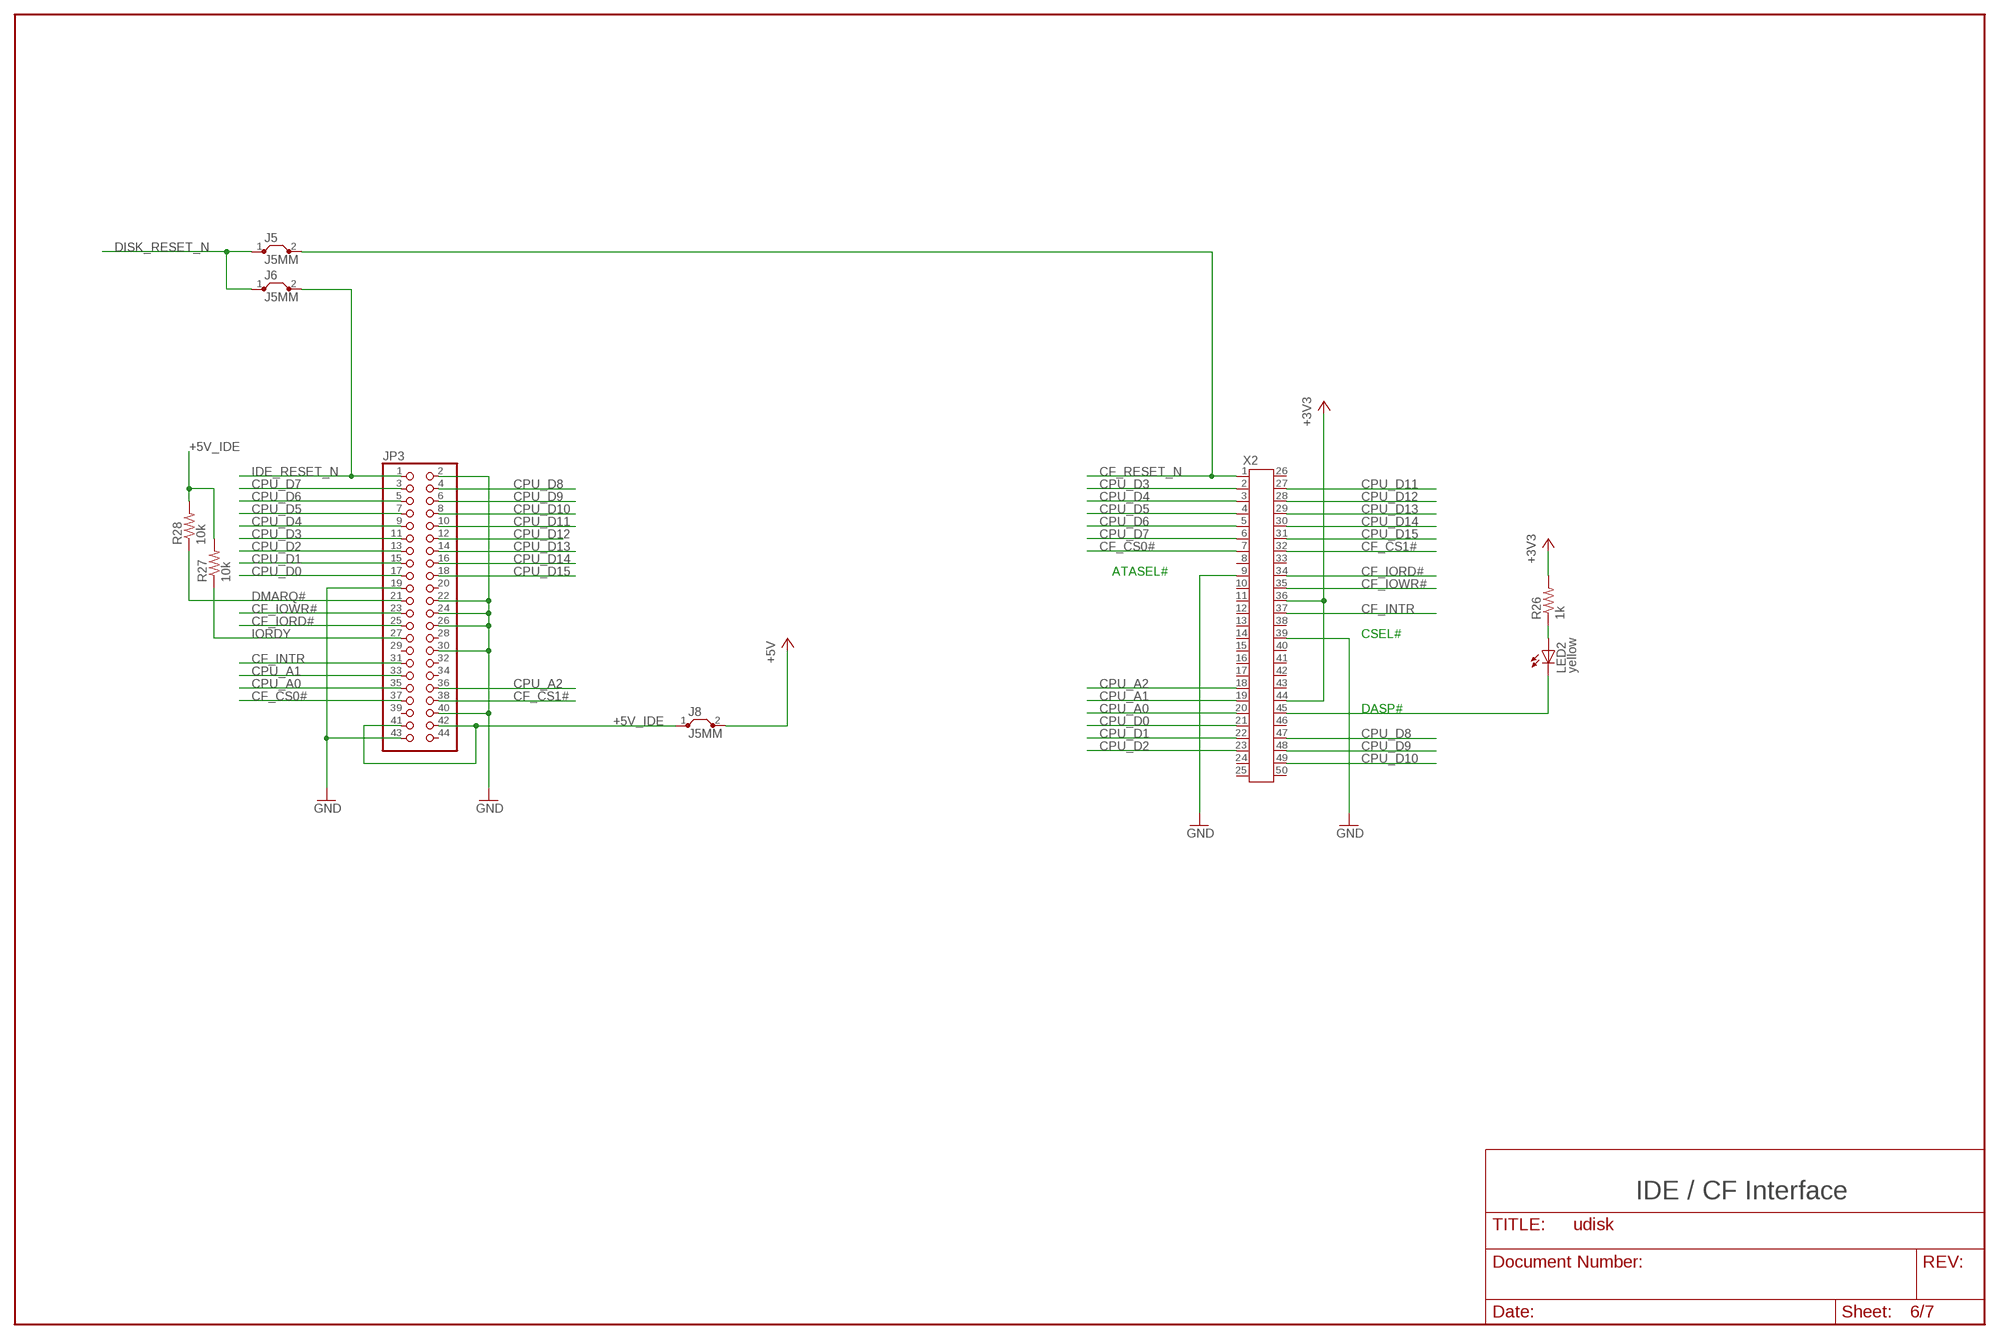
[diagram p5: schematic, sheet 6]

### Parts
J5  J5MM  [05]
J6  J5MM  [05]
J8  J5MM  [05]
JP3  PINHD-2X22  [2X22]
LED2  yellow  LEDB156  [Q62902-B156]
R26  1k  R-US_M0805  [M0805]
R27  10k  R-US_R0805  [R0805]
R28  10k  R-US_R0805  [R0805]
X2  N7E50516  [N7E50516]

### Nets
+3V3: R26.2 X2.36 X2.44 ; also sheet 1,2,5,7
+5V: J8.2 ; also sheet 3,4,5
+5V_IDE: J8.1 JP3.41 JP3.42 R27.2 R28.2
CF_CS0#: JP3.37 X2.7 ; also sheet 2
CF_CS1#: JP3.38 X2.32 ; also sheet 2
CF_INTR: JP3.31 X2.37
CF_IORD#: JP3.25 X2.34 ; also sheet 2
CF_IOWR#: JP3.23 X2.35 ; also sheet 2
CF_RESET_N: J5.2 X2.1
CPU_A0: JP3.35 X2.20 ; also sheet 1,2
CPU_A1: JP3.33 X2.19 ; also sheet 1,2
CPU_A2: JP3.36 X2.18 ; also sheet 1,2
CPU_D0: JP3.17 X2.21 ; also sheet 1,2
CPU_D1: JP3.15 X2.22 ; also sheet 1,2
CPU_D2: JP3.13 X2.23 ; also sheet 1,2
CPU_D3: JP3.11 X2.2 ; also sheet 1,2
CPU_D4: JP3.9 X2.3 ; also sheet 1,2
CPU_D5: JP3.7 X2.4 ; also sheet 1,2
CPU_D6: JP3.5 X2.5 ; also sheet 1,2
CPU_D7: JP3.3 X2.6 ; also sheet 1,2
CPU_D8: JP3.4 X2.47 ; also sheet 1,2
CPU_D9: JP3.6 X2.48 ; also sheet 1,2
CPU_D10: JP3.8 X2.49 ; also sheet 1,2
CPU_D11: JP3.10 X2.27 ; also sheet 1,2
CPU_D12: JP3.12 X2.28 ; also sheet 1,2
CPU_D13: JP3.14 X2.29 ; also sheet 1,2
CPU_D14: JP3.16 X2.30 ; also sheet 1,2
CPU_D15: JP3.18 X2.31 ; also sheet 1,2
DISK_RESET_N: J5.1 J6.1 ; also sheet 2
DMARQ#: JP3.21 R28.1
GND: JP3.2 JP3.19 JP3.22 JP3.24 JP3.26 JP3.30 JP3.40 JP3.43 X2.9 X2.39 ; also sheet 1,2,3,4,5,7
IDE_RESET_N: J6.2 JP3.1
IORDY: JP3.27 R27.1
N$17: LED2.A R26.1
N$70: LED2.K(C) X2.45
Unconnected: JP3.20 JP3.28 JP3.29 JP3.32 JP3.34 JP3.39 JP3.44 X2.8 X2.10 X2.11 X2.12 X2.13 X2.14 X2.15 X2.16 X2.17 X2.24 X2.25 X2.26 X2.33 X2.38 X2.40 X2.41 X2.42 X2.43 X2.46 X2.50

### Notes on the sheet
- ATASEL#
- CSEL#
- DASP#
- IDE / CF Interface

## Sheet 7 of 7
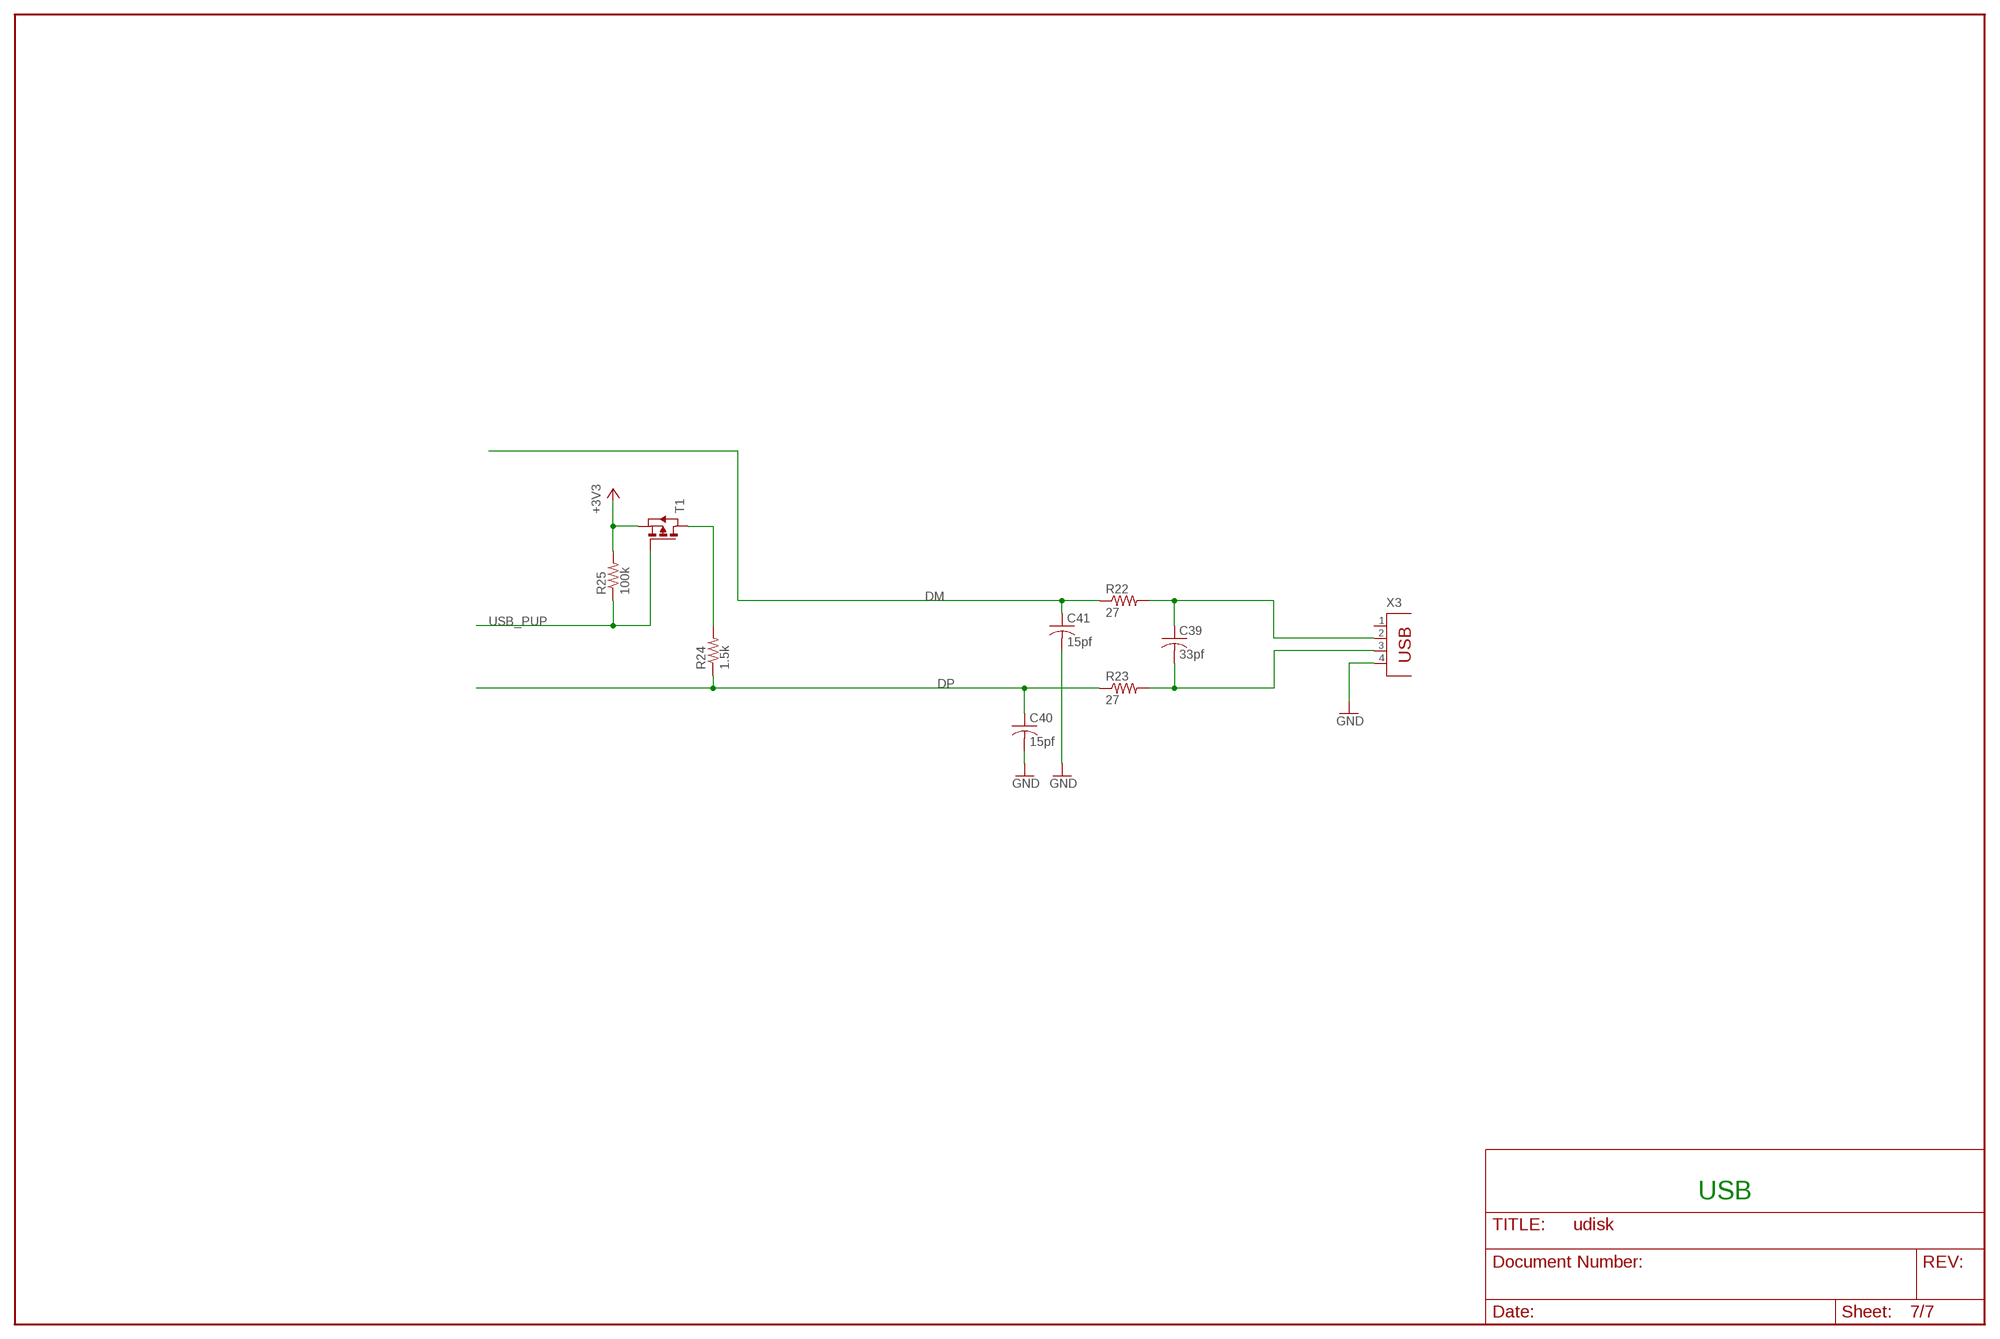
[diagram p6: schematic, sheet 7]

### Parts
C39  33pf  C-USC0805  [C0805]
C40  15pf  C-USC0805  [C0805]
C41  15pf  C-USC0805  [C0805]
R22  27  R-US_R0805  [R0805]
R23  27  R-US_R0805  [R0805]
R24  1.5k  R-US_R0805  [R0805]
R25  100k  R-US_R0805  [R0805]
T1  PMOSSOT23  [SOT-23]
X3  PN61729  [PN61729]

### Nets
+3V3: R25.2 T1.2(S) ; also sheet 1,2,5,6
DM: C41.1 R22.1 ; also sheet 1
DP: C40.1 R23.1 R24.1 ; also sheet 1
GND: C40.2 C41.2 X3.4 ; also sheet 1,2,3,4,5,6
N$51: C39.1 R22.2 X3.2
N$52: R24.2 T1.1(D)
N$53: C39.2 R23.2 X3.3
USB_PUP: R25.1 T1.3(G) ; also sheet 1
Unconnected: X3.1

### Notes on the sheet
- USB

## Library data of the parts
C1-C11 C14-C41 = rcl:C-US: CAPACITOR, American symbol
C12 C13 = rcl:CPOL-US: POLARIZED CAPACITOR, American symbol
D1 = 1SMA16AT3:1SMA16AT3: ZENER DIODE
IC1 = xcr3256xl:XCR3256XLTQ144
IC2-IC8 = unibus-dip:DS3862: Octal High Speed Trapezoidal Bus TransceiverBUS TRANSCEIVER
IC9 IC10 = unibus-dip:DS8641: Quad Unified Bus TransceiverBUS TRANSCEIVER
IC11 = lp8345:LP8345: VOLTAGE REGULATOR
IC12 = atmel_prototype_header:AT91SAM7S64: Atmel AT91 ARM Thumb-based Microcontroller. LQFP64 package.
IC13 = ti-max3221:MAX3221CPWR: RS-232 Line driver/receiver
J1-J9 = jumper:J: Bridge
JP1 = pinhead:PINHD-1X6: PIN HEADER
JP2 = pinhead:PINHD-2X10: PIN HEADER
JP3 = 2mm_2x22:PINHD-2X22: PIN HEADER
LED1-LED3 = led:LED: LED
Q1 = cts406:CTS406: CTS 406 CRYSTAL
R1-R33 = rcl:R-US_: RESISTOR, American symbol
S1 = itt-ksc241j:KSC241J: PUSH SWITCH ITT-Cannon
T1 = zetex:PMOSSOT23: MOS FET
U$1 = unibus-cdef:QUAD-CDEF: Quad-Height CDEF DEC Edge Connector
X1 = con-subd:F09HPS: SUB-D
X2 = 3M:N7E50516: 3M N7E50-7516-HG-40 Compact Flash Socket
X3 = con-berg:PN61729: BERG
